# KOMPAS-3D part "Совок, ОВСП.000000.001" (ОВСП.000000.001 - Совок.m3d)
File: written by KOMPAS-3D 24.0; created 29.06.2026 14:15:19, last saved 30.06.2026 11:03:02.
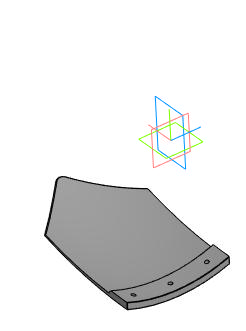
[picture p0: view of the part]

Document properties: Автор: user1; Полное имя файла: C:\Users\Админ\Desktop\Лопата\Лопата\КОМПАС\Совок.m3d

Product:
- Part/product: Совок  | designation ОВСП.000000.001
    Масса: 0.832152

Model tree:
1. Эскиз:1
2. Эскиз:2
3. Элемент по траектории:1
     Длина траектории = 221.736
4. Эскиз:5  (with: Грань.Элемент по траектории:1, Ребро.Элемент по траектории:1)
5. Эскиз:6
6. Элемент по траектории:2
     Длина траектории = 188.303
7. Фаска:2  (with: Ребро.Элемент по траектории:2)
     Угол = 45; Длина 1 = 4; Длина 2 = 4
8. Скругление:1  (with: Грань.Элемент по траектории:1)
     Радиус = 0.5
9. Эскиз:7  (with: Ребро.Элемент по траектории:2)
10. Элемент выдавливания:2
     Расстояние 2 = 500
11. Фаска:3  (with: Ребро.Элемент выдавливания:2)
     Угол = 45; Длина 1 = 1.5; Длина 2 = 1.5
12. Фаска:4  (with: Ребро.Элемент выдавливания:2)
     Угол = 45; Длина 1 = 0.3; Длина 2 = 0.3
13. Смещенная плоскость:7  (with: Грань.Элемент по траектории:1)
     Расстояние = 15
14. Эскиз:9  (with: Ребро.Скругление:1)
15. Перпендикулярная плоскость:1
16. Эскиз:10
17. Элемент выдавливания:3
     Расстояние 2 = 100
18. Зеркальный массив:1
19. Экземпляр ( 1 )
20. Экземпляр ( 2 )  (with: Элемент выдавливания:3)
21. Эскиз:11
22. Элемент выдавливания:4
     Расстояние 2 = 500
23. Фаска:5  (with: Ребро.Элемент выдавливания:3, Ребро.Элемент выдавливания:4)  (labels: Ребро.Элемент выдавливания:3.Экземпляр ( 2 ))
     Угол = 45; Длина 1 = 0.5; Длина 2 = 0.5

Expressions: 139/2
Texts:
  ОВСП.000000.001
